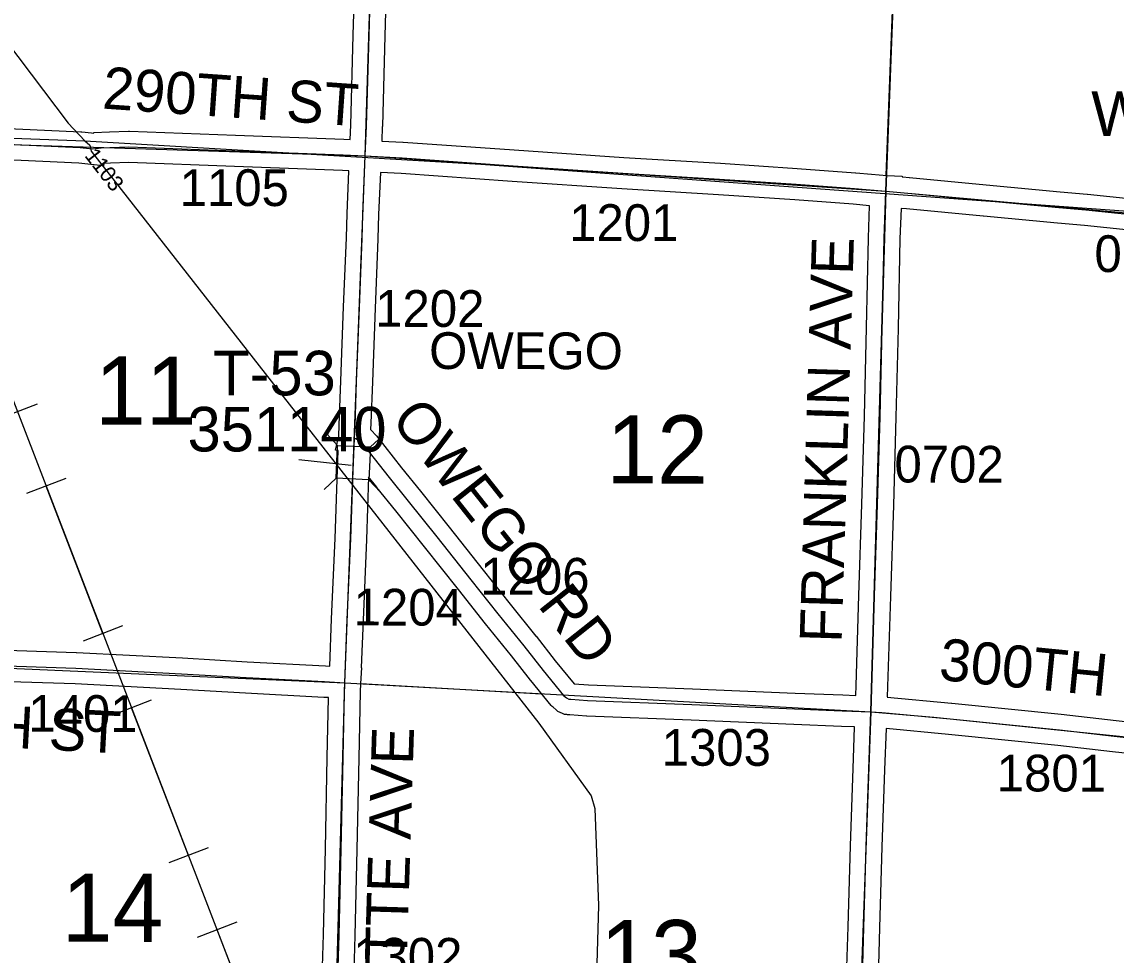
# Model space of a CAD drawing. Extents: x -157.2 to -99.3, y 12.2 to 46.2.
# Drawn here: x -136.617 to -134.532, y 20.323 to 22.102 of the extents above; entities that cross this region are included whole.
import ezdxf

# ---------------------------------------------------------------- set-up
doc = ezdxf.new("R2010")
doc.units = 0
for name, color, linetype in [('tdCoHydroRiver', 7, 'Continuous'), ('tdCoPipe', 7, 'Continuous'), ('tdCoSecRdNmbr', 7, 'Continuous'), ('tdCoSecRdTxt', 7, 'Continuous'), ('tdCoSecRteBand', 7, 'Continuous'), ('tdCoSecRteCL', 7, 'Continuous'), ('tdCoSectLine', 7, 'Continuous'), ('tdCoSectLinePart', 7, 'Continuous'), ('tdCoSectNmbr', 7, 'Continuous'), ('tdCoStrucSec', 7, 'Continuous'), ('tdCoStrucSecCoName', 7, 'Continuous'), ('tdCoStrucSecFHWANum', 7, 'Continuous'), ('tdCoSurfGravel', 7, 'Continuous'), ('tdCoSurfLNO', 7, 'Continuous'), ('tdCoTwpBndry', 7, 'Continuous'), ('tdCoTwpBndryShd', 7, 'Continuous'), ('tdCoUnicrpTwnTxt', 7, 'Continuous')]:
    doc.layers.add(name, color=color, linetype=linetype)

msp = doc.modelspace()

# ---------------------------------------------------------------- linework, layer by layer
at = {"layer": 'tdCoHydroRiver'}
for points in [[(-137.3184, 22.9212), (-136.696, 22.1291), (-136.5293, 21.909), (-136.4972, 21.8748)], [(-139.9196, 22.0213), (-138.8081, 21.9781), (-137.3896, 21.9079), (-136.4972, 21.8748)], [(-136.4972, 21.8748), (-136.488, 21.8667), (-136.4852, 21.8555), (-135.6322, 20.7655), (-135.5324, 20.6265), (-135.5253, 20.6026), (-135.5185, 20.4176), (-135.5357, 19.8164)], [(-136.4972, 21.8748), (-135.7425, 21.8304), (-134.4743, 21.7382)]]:
    msp.add_lwpolyline(points, dxfattribs=at)
at = {"layer": 'tdCoPipe'}
for p, q in [((-136.5882, 21.3735), (-136.6632, 21.3446)), ((-136.5335, 21.2316), (-136.6087, 21.2027)), ((-136.4253, 20.9507), (-136.5004, 20.9218)), ((-136.3706, 20.8088), (-136.4458, 20.7798)), ((-136.2624, 20.5279), (-136.3375, 20.4989)), ((-136.2078, 20.386), (-136.283, 20.357))]:
    msp.add_line(p, q, dxfattribs=at)
for points in [[(-135.1866, 16.5957), (-135.9454, 19.5928), (-136.6948, 21.5384), (-137.0121, 22.4903), (-136.934, 22.5495), (-137.7242, 24.8933)], [(-136.4629, 20.9362), (-136.5711, 21.2172)], [(-136.3, 20.5134), (-136.4082, 20.7943)], [(-136.1372, 20.0905), (-136.2454, 20.3715)]]:
    msp.add_lwpolyline(points, dxfattribs=at)
at = {"layer": 'tdCoSecRteBand'}
for points in [[(-135.9915, 21.8778), (-135.9904, 21.9048), (-135.9857, 22.0767), (-135.9857, 22.0767), (-135.9857, 22.0768), (-135.9803, 22.26)], [(-135.9203, 22.2582), (-135.9258, 22.075), (-135.9304, 21.9029), (-135.9304, 21.9027), (-135.9305, 21.9025), (-135.9316, 21.8746), (-135.8913, 21.8725), (-135.891, 21.8725), (-135.8908, 21.8724), (-135.679, 21.8576), (-135.4702, 21.8434), (-135.2861, 21.8323), (-135.286, 21.8323), (-135.2859, 21.8323), (-135.1399, 21.8224), (-135.1398, 21.8224), (-135.1397, 21.8224), (-135.0285, 21.814), (-135.0283, 21.814), (-135.0282, 21.814), (-134.9983, 21.8114), (-134.9691, 21.809), (-134.9399, 21.8079), (-134.9399, 21.8065), (-134.9385, 21.8064), (-134.9263, 21.8053), (-134.9262, 21.8053), (-134.926, 21.8053), (-134.7796, 21.7912), (-134.6386, 21.7779), (-134.5872, 21.7735), (-134.587, 21.7735), (-134.5867, 21.7735), (-134.4468, 21.7589)], [(-136.6856, 21.9006), (-136.5051, 21.8925), (-136.5041, 21.8924), (-136.5031, 21.8923), (-136.4848, 21.8903), (-136.4803, 21.8898), (-136.4804, 21.891), (-136.4504, 21.8921), (-136.4143, 21.8935), (-136.4132, 21.8935), (-136.4121, 21.8935), (-136.2101, 21.8858), (-136.004, 21.8784), (-136.0037, 21.8784), (-136.0035, 21.8784), (-135.9915, 21.8778)], [(-136.0306, 20.874), (-136.0272, 20.9641), (-136.0271, 20.9642), (-136.0271, 20.9642), (-136.0205, 21.1175), (-136.0161, 21.2485), (-136.0161, 21.2487), (-136.016, 21.2488), (-136.0145, 21.2846), (-136.0196, 21.2858), (-136.0133, 21.3122), (-136.0124, 21.3333), (-136.0094, 21.4178), (-136.0094, 21.4178), (-136.0094, 21.4178), (-136.0042, 21.5586), (-136.0042, 21.5587), (-136.0042, 21.5588), (-135.9988, 21.6901), (-135.9973, 21.7365), (-135.9973, 21.7367), (-135.9973, 21.7368), (-135.994, 21.8175), (-135.994, 21.8178), (-135.9943, 21.8178), (-136.0064, 21.8185), (-136.2123, 21.8259), (-136.2123, 21.8259), (-136.2124, 21.8259), (-136.4132, 21.8335), (-136.4482, 21.8322), (-136.4612, 21.8317), (-136.4617, 21.8273), (-136.4915, 21.8306), (-136.5088, 21.8326), (-136.688, 21.8406)], [(-135.0284, 20.8179), (-135.0277, 20.8369), (-135.0223, 21.0087), (-135.0223, 21.0087), (-135.0223, 21.0087), (-135.0166, 21.1828), (-135.0119, 21.3501), (-135.0077, 21.5192), (-135.004, 21.6898), (-135.004, 21.69), (-135.004, 21.6902), (-135.0019, 21.7515), (-135.0331, 21.7542), (-135.1441, 21.7625), (-135.2899, 21.7724), (-135.474, 21.7835), (-135.4741, 21.7835), (-135.4742, 21.7835), (-135.6831, 21.7978), (-135.6831, 21.7978), (-135.6831, 21.7978), (-135.8947, 21.8126), (-135.9341, 21.8146), (-135.9374, 21.7345), (-135.9388, 21.688), (-135.9388, 21.6879), (-135.9388, 21.6877), (-135.9443, 21.5563), (-135.9494, 21.4156), (-135.9522, 21.3367), (-135.9521, 21.3367), (-135.9527, 21.3251), (-135.951, 21.3232), (-135.9429, 21.3141), (-135.9423, 21.3134), (-135.9417, 21.3127), (-135.894, 21.2522), (-135.8579, 21.2074), (-135.8578, 21.2074), (-135.8578, 21.2074), (-135.803, 21.139), (-135.803, 21.139), (-135.8029, 21.1389), (-135.7381, 21.057), (-135.7381, 21.057), (-135.7381, 21.057), (-135.6868, 20.9923), (-135.6376, 20.9312), (-135.6375, 20.9311), (-135.6374, 20.9309), (-135.6008, 20.8843), (-135.5647, 20.8404), (-135.5377, 20.8385), (-135.3397, 20.8307), (-135.3397, 20.8307), (-135.3396, 20.8307), (-135.1439, 20.8225), (-135.0532, 20.8191), (-135.0531, 20.8191), (-135.053, 20.8191), (-135.0284, 20.8179)], [(-134.4528, 21.6992), (-134.5926, 21.7138), (-134.6439, 21.7182), (-134.644, 21.7182), (-134.6442, 21.7182), (-134.7852, 21.7315), (-134.7852, 21.7315), (-134.7853, 21.7315), (-134.9316, 21.7456), (-134.942, 21.7464), (-134.944, 21.6883), (-134.9477, 21.5178), (-134.9477, 21.5178), (-134.9477, 21.5177), (-134.9519, 21.3486), (-134.9519, 21.3485), (-134.9519, 21.3485), (-134.9566, 21.181), (-134.9566, 21.181), (-134.9566, 21.1809), (-134.9623, 21.0068), (-134.9677, 20.8349), (-134.9677, 20.8349), (-134.9677, 20.8348), (-134.9684, 20.8152), (-134.9681, 20.8152), (-134.9682, 20.8148), (-134.8457, 20.8037), (-134.8455, 20.8037), (-134.8453, 20.8036), (-134.6369, 20.7822), (-134.6368, 20.7822), (-134.6367, 20.7822), (-134.5324, 20.7706), (-134.5324, 20.7706), (-134.5324, 20.7706), (-134.403, 20.7561)], [(-135.0457, 20.2817), (-135.0427, 20.3769), (-135.0383, 20.5312), (-135.0383, 20.5313), (-135.0383, 20.5313), (-135.0334, 20.6786), (-135.0334, 20.6786), (-135.0334, 20.6786), (-135.0305, 20.7577), (-135.0305, 20.758), (-135.0308, 20.758), (-135.0556, 20.7591), (-135.1462, 20.7626), (-135.1463, 20.7626), (-135.1463, 20.7626), (-135.3421, 20.7707), (-135.5406, 20.7786), (-135.541, 20.7786), (-135.5415, 20.7786), (-135.5731, 20.7809), (-135.5738, 20.7809), (-135.5745, 20.781), (-135.5775, 20.7814), (-135.5787, 20.7815), (-135.5832, 20.782), (-135.5873, 20.7839), (-135.5918, 20.7858), (-135.5959, 20.7877), (-135.5993, 20.7906), (-135.6049, 20.7956), (-135.6068, 20.7972), (-135.6084, 20.7991), (-135.6474, 20.8465), (-135.6476, 20.8467), (-135.6478, 20.847), (-135.6844, 20.8937), (-135.7336, 20.9547), (-135.7337, 20.9548), (-135.7338, 20.9549), (-135.7851, 21.0198), (-135.8499, 21.1016), (-135.9046, 21.1698), (-135.9408, 21.2146), (-135.9409, 21.2148), (-135.941, 21.2149), (-135.9565, 21.2346), (-135.9605, 21.1153), (-135.9605, 21.1152), (-135.9605, 21.115), (-135.9672, 20.9617), (-135.9706, 20.8711), (-135.9706, 20.8706), (-135.9701, 20.8705), (-135.9718, 20.8409), (-135.9724, 20.8252), (-135.9753, 20.6984), (-135.979, 20.5246), (-135.979, 20.5246), (-135.979, 20.5245), (-135.9827, 20.3608), (-135.9827, 20.3607), (-135.9827, 20.3606), (-135.9881, 20.1776)], [(-136.7214, 20.9068), (-136.5138, 20.9001), (-136.5135, 20.9001), (-136.5132, 20.9001), (-136.3112, 20.8895), (-136.3111, 20.8895), (-136.311, 20.8895), (-136.188, 20.8823), (-136.0387, 20.8744), (-136.0386, 20.8744), (-136.0386, 20.8744), (-136.0306, 20.874)], [(-136.0481, 20.1794), (-136.0427, 20.3623), (-136.039, 20.5259), (-136.0353, 20.6997), (-136.0353, 20.6997), (-136.0353, 20.6998), (-136.0327, 20.8134), (-136.0329, 20.8134), (-136.0328, 20.814), (-136.0419, 20.8145), (-136.1913, 20.8224), (-136.1914, 20.8224), (-136.1914, 20.8224), (-136.3144, 20.8296), (-136.516, 20.8401), (-136.7233, 20.8468)], [(-134.4093, 20.6964), (-134.539, 20.7109), (-134.6432, 20.7225), (-134.8513, 20.7439), (-134.9706, 20.7548), (-134.9734, 20.6765), (-134.9783, 20.5294), (-134.9828, 20.3751), (-134.9828, 20.3751), (-134.9828, 20.375), (-134.9857, 20.2798)]]:
    msp.add_lwpolyline(points, dxfattribs=at)
at = {"layer": 'tdCoSecRteCL'}
for points in [[(-135.9628, 21.8462), (-135.9604, 21.9038), (-135.9557, 22.0759), (-135.9503, 22.2591), (-135.9451, 22.4307), (-135.9382, 22.609), (-135.9328, 22.7942), (-135.9313, 22.8553)], [(-136.9585, 21.8783), (-136.8889, 21.8756), (-136.6869, 21.8706), (-136.5064, 21.8625), (-136.4881, 21.8604)], [(-136.4493, 21.8621), (-136.4132, 21.8635), (-136.2112, 21.8558), (-136.0051, 21.8484), (-135.9628, 21.8462)], [(-135.9834, 21.308), (-135.9824, 21.3321), (-135.9794, 21.4167), (-135.9742, 21.5575), (-135.9688, 21.689), (-135.9673, 21.7356), (-135.9628, 21.8462)], [(-135.9628, 21.8462), (-135.8929, 21.8425), (-135.681, 21.8277), (-135.4722, 21.8134), (-135.2879, 21.8023), (-135.1419, 21.7925), (-135.0307, 21.7841), (-134.9709, 21.779)], [(-134.9995, 20.7866), (-134.9977, 20.8359), (-134.9923, 21.0078), (-134.9866, 21.1819), (-134.9819, 21.3493), (-134.9777, 21.5185), (-134.974, 21.6891), (-134.9709, 21.779)], [(-134.9709, 21.779), (-134.9289, 21.7754), (-134.7824, 21.7614), (-134.6413, 21.7481), (-134.5898, 21.7436), (-134.4497, 21.7291), (-134.318, 21.7172), (-134.2009, 21.7079), (-134.0653, 21.6965), (-134.0339, 21.6941), (-134.028, 21.6938)], [(-136.0017, 20.8423), (-135.9972, 20.9629), (-135.9905, 21.1163), (-135.9861, 21.2475), (-135.9834, 21.308)], [(-135.9834, 21.308), (-135.9811, 21.3075), (-135.9734, 21.3033), (-135.9653, 21.2941), (-135.9174, 21.2335), (-135.8812, 21.1886), (-135.8264, 21.1203), (-135.7616, 21.0384), (-135.7103, 20.9736), (-135.661, 20.9124), (-135.6242, 20.8655), (-135.5853, 20.8182), (-135.5796, 20.8133), (-135.5751, 20.8113), (-135.574, 20.8111), (-135.571, 20.8108), (-135.5394, 20.8086), (-135.3409, 20.8007), (-135.1451, 20.7925), (-135.0543, 20.7891), (-134.9995, 20.7866)], [(-136.9905, 20.8855), (-136.9209, 20.8832), (-136.7224, 20.8768), (-136.5147, 20.8701), (-136.3128, 20.8595), (-136.1897, 20.8524), (-136.0403, 20.8445), (-136.0017, 20.8423)], [(-136.0287, 19.8393), (-136.0248, 19.9499), (-136.0236, 20.0024), (-136.0181, 20.1785), (-136.0127, 20.3615), (-136.009, 20.5252), (-136.0053, 20.6991), (-136.0024, 20.8261), (-136.0017, 20.8423)], [(-135.0352, 19.7869), (-135.034, 19.8697), (-135.0332, 19.9414), (-135.0325, 19.9742), (-135.0305, 20.0014), (-135.0285, 20.0339), (-135.0241, 20.0825), (-135.0216, 20.0973), (-135.0209, 20.1197), (-135.0157, 20.2808), (-135.0127, 20.376), (-135.0083, 20.5303), (-135.0034, 20.6776), (-134.9995, 20.7866)], [(-134.9995, 20.7866), (-134.9784, 20.7856), (-134.8484, 20.7738), (-134.64, 20.7523), (-134.5357, 20.7408), (-134.406, 20.7262), (-134.3512, 20.7213), (-134.3397, 20.7213)]]:
    msp.add_lwpolyline(points, dxfattribs=at)
at = {"layer": 'tdCoSectLine'}
for points in [[(-135.9632, 21.8462), (-135.9317, 22.8553)], [(-134.9713, 21.779), (-134.9318, 22.8156)], [(-136.9588, 21.8783), (-135.9632, 21.8462)], [(-136.0021, 20.8423), (-135.9632, 21.8462)], [(-135.9632, 21.8462), (-134.9713, 21.779)], [(-134.9998, 20.7866), (-134.9713, 21.779)], [(-134.9713, 21.779), (-134.0284, 21.6938)], [(-136.9909, 20.8855), (-136.0021, 20.8423)], [(-136.0291, 19.8393), (-136.0021, 20.8423)], [(-136.0021, 20.8423), (-134.9998, 20.7866)], [(-134.9998, 20.7866), (-135.0355, 19.7869)], [(-134.9998, 20.7866), (-134.8795, 20.7766), (-134.067, 20.6937)]]:
    msp.add_lwpolyline(points, dxfattribs=at)
at = {"layer": 'tdCoSectLinePart'}
for points in [[(-134.9701, 21.809), (-134.9329, 22.7854)], [(-135.9722, 20.8406), (-135.6271, 20.8214)]]:
    msp.add_lwpolyline(points, dxfattribs=at)
at = {"layer": 'tdCoStrucSec'}
for p, q in [((-136.0157, 21.2945), (-136.0369, 21.3175)), ((-135.9532, 21.2917), (-135.9301, 21.3129)), ((-136.0185, 21.2319), (-136.0415, 21.2108)), ((-135.9559, 21.2292), (-135.9348, 21.2061))]:
    msp.add_line(p, q, dxfattribs=at)
msp.add_lwpolyline([(-136.0185, 21.2319), (-136.0157, 21.2945), (-135.9532, 21.2917), (-135.9559, 21.2292)], close=True, dxfattribs=at)
at = {"layer": 'tdCoStrucSecFHWANum'}
msp.add_line((-136.0897, 21.268), (-135.9895, 21.2571), dxfattribs=at)
at = {"layer": 'tdCoSurfGravel'}
for points in [[(-136.0181, 20.1785), (-136.0127, 20.3615), (-136.009, 20.5252), (-136.0053, 20.6991), (-136.0024, 20.8261), (-136.0017, 20.8423), (-135.9972, 20.9629), (-135.9905, 21.1163), (-135.9861, 21.2475), (-135.9834, 21.308), (-135.9824, 21.3321), (-135.9794, 21.4167), (-135.9742, 21.5575), (-135.9688, 21.689), (-135.9673, 21.7356), (-135.9628, 21.8462), (-135.9604, 21.9038), (-135.9557, 22.0759), (-135.9503, 22.2591), (-135.9451, 22.4307), (-135.9382, 22.609), (-135.9328, 22.7942), (-135.9313, 22.8553)], [(-136.9585, 21.8783), (-136.8889, 21.8756), (-136.6869, 21.8706), (-136.5064, 21.8625), (-136.4881, 21.8604)], [(-136.4493, 21.8621), (-136.4132, 21.8635), (-136.2112, 21.8558), (-136.0051, 21.8484), (-135.9628, 21.8462), (-135.8929, 21.8425), (-135.681, 21.8277), (-135.4722, 21.8134), (-135.2879, 21.8023), (-135.1419, 21.7925), (-135.0307, 21.7841), (-134.9709, 21.779)], [(-134.9995, 20.7866), (-134.9977, 20.8359), (-134.9923, 21.0078), (-134.9866, 21.1819), (-134.9819, 21.3493), (-134.9777, 21.5185), (-134.974, 21.6891), (-134.9709, 21.779)], [(-134.9709, 21.779), (-134.9289, 21.7754), (-134.7824, 21.7614), (-134.6413, 21.7481), (-134.5898, 21.7436), (-134.4497, 21.7291), (-134.318, 21.7172), (-134.2009, 21.7079), (-134.0653, 21.6965), (-134.0339, 21.6941), (-134.028, 21.6938), (-134.0182, 21.6933), (-133.8724, 21.6936), (-133.6707, 21.6936), (-133.5348, 21.6943), (-133.4746, 21.6938), (-133.4162, 21.6947)], [(-135.9834, 21.308), (-135.9811, 21.3075), (-135.9734, 21.3033), (-135.9653, 21.2941), (-135.9174, 21.2335), (-135.8812, 21.1886), (-135.8264, 21.1203), (-135.7616, 21.0384), (-135.7103, 20.9736), (-135.661, 20.9124), (-135.6242, 20.8655), (-135.5853, 20.8182), (-135.5796, 20.8133), (-135.5751, 20.8113), (-135.574, 20.8111)], [(-137.9913, 20.919), (-137.8962, 20.9152), (-137.782, 20.9115), (-137.5221, 20.9024), (-137.3552, 20.897), (-137.2427, 20.8938), (-137.1157, 20.8896), (-136.9905, 20.8855), (-136.9209, 20.8832), (-136.7224, 20.8768), (-136.5147, 20.8701), (-136.3128, 20.8595), (-136.1897, 20.8524), (-136.0403, 20.8445), (-136.0017, 20.8423)], [(-135.574, 20.8111), (-135.571, 20.8108), (-135.5394, 20.8086), (-135.3409, 20.8007), (-135.1451, 20.7925), (-135.0543, 20.7891), (-134.9995, 20.7866)], [(-135.0157, 20.2808), (-135.0127, 20.376), (-135.0083, 20.5303), (-135.0034, 20.6776), (-134.9995, 20.7866)], [(-134.9995, 20.7866), (-134.9784, 20.7856), (-134.8484, 20.7738), (-134.64, 20.7523), (-134.5357, 20.7408), (-134.406, 20.7262), (-134.3512, 20.7213), (-134.3397, 20.7213)]]:
    msp.add_lwpolyline(points, dxfattribs=at)
at = {"layer": 'tdCoSurfLNO'}
msp.add_lwpolyline([(-136.4881, 21.8604), (-136.4881, 21.8604), (-136.4823, 21.8598), (-136.4662, 21.8615), (-136.4494, 21.8621), (-136.4493, 21.8621)], dxfattribs=at)
at = {"layer": 'tdCoTwpBndry'}
msp.add_lwpolyline([(-134.9701, 21.809), (-134.9329, 22.7856)], dxfattribs=at)
at = {"layer": 'tdCoTwpBndryShd'}
msp.add_lwpolyline([(-134.5827, 34.8376), (-134.6206, 33.6622), (-134.6624, 32.6731), (-134.702, 31.6829), (-134.7248, 30.6831), (-134.7505, 29.6994), (-134.7778, 28.6994), (-134.8012, 27.7577), (-134.8314, 26.7672), (-134.8649, 25.7715), (-134.8895, 24.789), (-134.9097, 23.8132), (-134.9318, 22.8156), (-134.9713, 21.779), (-134.9998, 20.7866), (-135.0355, 19.7869), (-135.0694, 18.8043), (-135.1107, 17.815), (-135.1553, 16.8138)], dxfattribs=at)

# ---------------------------------------------------------------- texts
at = {"layer": 'tdCoSecRdNmbr'}
for s, height, rotation, p in [('1103', 0.03, 307.7487, (-136.499, 21.8465)), ('1105', 0.07, 359.8964, (-136.3167, 21.7511)), ('1201', 0.07, 359.8973, (-135.5745, 21.6844)), ('0701', 0.07, 359.898, (-134.5735, 21.6251)), ('1202', 0.07, 359.897, (-135.9441, 21.5207)), ('0702', 0.07, 359.8978, (-134.9546, 21.224)), ('1206', 0.07, 359.8972, (-135.7439, 21.0105)), ('1204', 0.07, 359.897, (-135.9852, 20.9515)), ('1401', 0.07, 359.8966, (-136.6051, 20.7489)), ('1303', 0.07, 359.8975, (-135.3981, 20.6843)), ('1801', 0.07, 359.898, (-134.7597, 20.6353)), ('1302', 0.07, 359.897, (-135.9861, 20.2862))]:
    msp.add_text(s, height=height, rotation=rotation, dxfattribs=at).set_placement(p)
at = {"layer": 'tdCoSecRdTxt'}
for s, rotation, p in [('290TH ST', 356.0083, (-136.4653, 21.9367)), ('FRANKLIN AVE', 88.2524, (-135.0553, 20.9179)), ('OWEGO RD', 308.3894, (-135.9163, 21.3435)), ('300TH ST', 354.3657, (-134.8715, 20.848)), ('300TH ST', 356.996, (-136.9177, 20.733)), ('FAYETTE AVE', 88.2024, (-135.8926, 20.0318))]:
    msp.add_text(s, height=0.08, rotation=rotation, dxfattribs=at).set_placement(p)
at = {"layer": 'tdCoSectNmbr'}
for s, rotation, p in [('11', 359.8965, (-136.4781, 21.3342)), ('12', 359.8973, (-135.5035, 21.2222)), ('14', 359.8966, (-136.5414, 20.3488)), ('13', 359.8974, (-135.5152, 20.2604))]:
    msp.add_text(s, height=0.13, rotation=rotation, dxfattribs=at).set_placement(p)
at = {"layer": 'tdCoStrucSecCoName'}
for s, p in [('WILLOW U-17-1', (-134.5796, 21.8842)), ('T-53', (-136.2528, 21.39))]:
    msp.add_text(s, height=0.085, dxfattribs=at).set_placement(p)
at = {"layer": 'tdCoStrucSecFHWANum'}
msp.add_text('351140', height=0.085, dxfattribs=at).set_placement((-136.3016, 21.2831))
at = {"layer": 'tdCoUnicrpTwnTxt'}
msp.add_text('OWEGO', height=0.07, rotation=359.8972, dxfattribs=at).set_placement((-135.8413, 21.4403))

doc.saveas('drawing.dxf')
